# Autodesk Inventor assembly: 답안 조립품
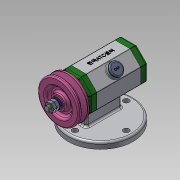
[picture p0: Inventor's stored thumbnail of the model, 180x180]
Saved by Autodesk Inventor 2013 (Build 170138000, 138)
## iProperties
Created: 2021-02
Part Number: 답안 조립품
Document SubType Name: Assembly
Designer: default
Author: default
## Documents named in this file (14)
- C:\Users\default.default-PC\Desktop\710204V1016\답안 조립품.iam
- C:\Users\default.default-PC\Desktop\710204V1016\본체.ipt
- C:\Users\default.default-PC\Desktop\710204V1016\앞커버.ipt
- C:\Users\default.default-PC\Desktop\710204V1016\뒤커버.ipt
- C:\Users\default.default-PC\Desktop\710204V1016\베어링 15 x 32 x 9.ipt
- C:\Users\default.default-PC\Desktop\710204V1016\축.ipt
- C:\Users\default.default-PC\Desktop\710204V1016\오일 실 15 25 7.ipt
- C:\Users\default.default-PC\Desktop\710204V1016\키 3 x 3 x 12.ipt
- C:\Users\default.default-PC\Desktop\710204V1016\V벨트풀리.ipt
- C:\Users\default.default-PC\Desktop\710204V1016\와셔 8x17.ipt
- C:\Users\default.default-PC\Desktop\710204V1016\스프링와셔 8.ipt
- C:\Users\default.default-PC\Desktop\710204V1016\너트 M8.ipt
- C:\Users\default.default-PC\Desktop\710204V1016\볼트 M4 x 12.ipt
- C:\Users\default.default-PC\Desktop\710204V1016\고무캡.ipt
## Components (2 placed, 2 different names)
1. V벨트풀리:1 — 각도:2
2. 고무캡:1
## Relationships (1: Angle 1)
- 각도:2 [Angle]: V벨트풀리:1
